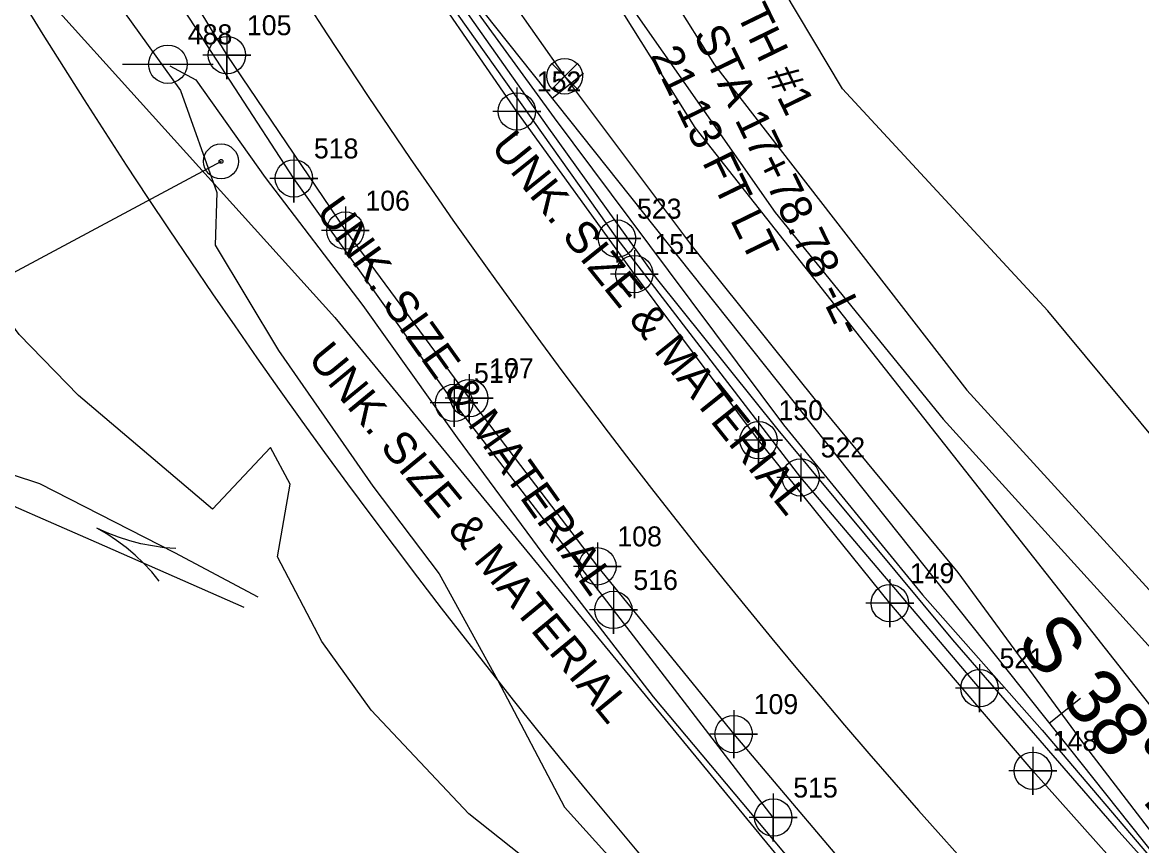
# Model space of a CAD drawing. Extents: x 1534145 to 1537876, y 509021 to 513201.
# Drawn here: x 1536125.4 to 1536265.6, y 511546.2 to 511649.3 of the extents above; entities that cross this region are included whole.
import ezdxf

# ---------------------------------------------------------------- set-up
doc = ezdxf.new("R2010")
doc.units = 0
for name, color, linetype in [('Exist Guardrail', 7, 'Continuous'), ('Exist Guardrail Cogo Number', 7, 'Continuous'), ('Exist Guardrail Cogo Point CELL', 7, 'Continuous'), ('Exist Horizontal Alignment', 7, 'Continuous'), ('Exist Horizontal Baseline Alignment', 7, 'Continuous'), ('Exist Horizontal Baseline Alignment Direction Label', 7, 'Continuous'), ('Exist Horizontal Baseline Alignment Tick small', 7, 'Continuous'), ('Exist Hydro Stream Flow Arrow CELL', 7, 'Continuous'), ('Exist Hydro Stream or Body of Water', 7, 'Continuous'), ('Exist Right of Way Line', 7, 'Continuous'), ('Exist Roads EOP', 7, 'Continuous'), ('Exist Roads EOP Cogo Number', 7, 'Continuous'), ('Exist Roads EOP Cogo Point CELL', 7, 'Continuous'), ('Exist Utilities Other Located Object CELL', 7, 'Continuous'), ('Exist Utilities Other Located Object Leader', 7, 'Continuous'), ('Exist Utilities Telephone Pole CELL', 7, 'Continuous'), ('Exist Utilities Telephone Pole Cogo Number', 7, 'Continuous'), ('Exist Utilities Telephone UG Cable', 7, 'Continuous'), ('Exist Utilities Telephone UG Cable Text', 7, 'Continuous'), ('Exist Utilities Telephone UG FO SUE', 7, 'Continuous'), ('Exist Utilities Telephone UG FO SUE Text', 7, 'Continuous'), ('Exist Utilities TV UG Cable', 7, 'Continuous'), ('Exist Utilities Water Test Hole SUE Text', 7, 'Continuous'), ('Exist Utilities Water UG Line SUE', 7, 'Continuous'), ('Exist Utilities Water Valve CELL', 7, 'Continuous'), ('Exist Vegetation Woods Line', 7, 'Continuous')]:
    doc.layers.add(name, color=color, linetype=linetype)

# ---------------------------------------------------------------- blocks, each defined once
blk = doc.blocks.new('EXIST UTILITIES TELEPHONE POLE')
at = {"layer": 'Exist Utilities Telephone Pole CELL'}
for p, q in [((-0.1135, 0), (0.11325, 0)), ((0, 0), (0, 0))]:
    blk.add_line(p, q, dxfattribs=at)
blk.add_circle((0, 0), 0.04813, dxfattribs=at)
blk = doc.blocks.new('EXIST UTILITIES OTHER LOCATED OBJECT')
at = {"layer": 'Exist Utilities Other Located Object CELL'}
for radius in [0.0436, 0.0048]:
    blk.add_circle((0, 0), radius, dxfattribs=at)

msp = doc.modelspace()

# ---------------------------------------------------------------- linework, layer by layer
at = {"layer": 'Exist Guardrail'}
for points in [[(1536245.27, 511565.91), (1536222.87, 511592.31), (1536199.87, 511622.21), (1536168.21, 511666.86), (1536157.96, 511682.31)], [(1536219.44, 511549.72), (1536199.42, 511575.71), (1536179.46, 511601.63), (1536159.41, 511629.75), (1536144.62, 511652.49), (1536134.97, 511668.45)]]:
    msp.add_lwpolyline(points, dxfattribs=at)
at = {"layer": 'Exist Guardrail Cogo Point CELL'}
for points in [[(1536159.41, 511632.75), (1536159.41, 511626.75), (1536159.41, 511629.75), (1536162.41, 511629.75), (1536156.41, 511629.75)], [(1536199.87, 511625.21), (1536199.87, 511619.21), (1536199.87, 511622.21), (1536202.87, 511622.21), (1536196.87, 511622.21)], [(1536179.46, 511604.63), (1536179.46, 511598.63), (1536179.46, 511601.63), (1536182.46, 511601.63), (1536176.46, 511601.63)], [(1536222.87, 511595.31), (1536222.87, 511589.31), (1536222.87, 511592.31), (1536225.87, 511592.31), (1536219.87, 511592.31)], [(1536199.42, 511578.71), (1536199.42, 511572.71), (1536199.42, 511575.71), (1536202.42, 511575.71), (1536196.42, 511575.71)], [(1536245.27, 511568.91), (1536245.27, 511562.91), (1536245.27, 511565.91), (1536248.27, 511565.91), (1536242.27, 511565.91)], [(1536219.44, 511552.72), (1536219.44, 511546.72), (1536219.44, 511549.72), (1536222.44, 511549.72), (1536216.44, 511549.72)]]:
    msp.add_lwpolyline(points, dxfattribs=at)
for centre in [(1536159.41, 511629.75), (1536199.87, 511622.21), (1536179.46, 511601.63), (1536222.87, 511592.31), (1536199.42, 511575.71), (1536245.27, 511565.91), (1536219.44, 511549.72)]:
    msp.add_circle(centre, 2.34, dxfattribs=at)
at = {"layer": 'Exist Horizontal Alignment'}
msp.add_arc((1536874.85, 512113.15), 850, 183.46397, 223.9944, dxfattribs=at)
at = {"layer": 'Exist Horizontal Baseline Alignment'}
msp.add_line((1536066.28, 511797.6), (1536449.44, 511315.8), dxfattribs=at)
at = {"layer": 'Exist Horizontal Baseline Alignment Tick small'}
for p, q in [((1536191.76, 511639.81), (1536195.67, 511642.93)), ((1536254, 511561.55), (1536257.92, 511564.66))]:
    msp.add_line(p, q, dxfattribs=at)
at = {"layer": 'Exist Hydro Stream Flow Arrow CELL'}
msp.add_line((1536139.14, 511583.67), (1536139.14, 511583.67), dxfattribs=at)
for points in [[(1536144.63, 511583.39), (1536143.17, 511583.48), (1536141.69, 511583.72), (1536140.24, 511583.99), (1536138.84, 511584.36), (1536137.43, 511584.82), (1536136.04, 511585.37), (1536134.71, 511585.97)], [(1536142.52, 511579.33), (1536141.61, 511580.48), (1536140.56, 511581.55), (1536139.51, 511582.59), (1536138.4, 511583.52), (1536137.21, 511584.4), (1536135.97, 511585.23), (1536134.71, 511585.97)]]:
    msp.add_lwpolyline(points, dxfattribs=at)
at = {"layer": 'Exist Hydro Stream or Body of Water'}
for points in [[(1536113.56, 511596.13), (1536127.55, 511591.56), (1536144.46, 511582.92), (1536154.87, 511577.37)], [(1536111.59, 511594.19), (1536118.18, 511591.38), (1536134.65, 511584.19), (1536153.12, 511576.06)]]:
    msp.add_lwpolyline(points, dxfattribs=at)
at = {"layer": 'Exist Right of Way Line'}
msp.add_lwpolyline([(1536145.81, 511737.79), (1536209.6, 511636.11), (1536268.44, 511561.44), (1536375.73, 511456.33), (1536489.24, 511358.86)], dxfattribs=at)
msp.add_arc((1536874.85, 512113.15), 880, 183.46397, 223.9944, dxfattribs=at)
at = {"layer": 'Exist Roads EOP'}
for points in [[(1536369.08, 511439.8), (1536328.72, 511476.49), (1536308.15, 511496.03), (1536288.57, 511515.64), (1536269.45, 511535.94), (1536251.94, 511555.57), (1536234.04, 511576.56), (1536217.6, 511596.97), (1536202.04, 511617.77), (1536187.32, 511638.14), (1536172.57, 511659.55), (1536157.27, 511681.68), (1536156.29, 511681.96)], [(1536135.62, 511669.8), (1536136.84, 511668.44), (1536151.02, 511645.18), (1536165.85, 511623.21), (1536181.37, 511602.23), (1536197.41, 511581.17), (1536214.48, 511560.17), (1536232.66, 511538.69), (1536250.52, 511518.58), (1536269.89, 511498.04), (1536290.03, 511477.85), (1536311.06, 511457.59), (1536352.37, 511420.24), (1536394.3, 511383.89), (1536395.14, 511383.19)]]:
    msp.add_lwpolyline(points, dxfattribs=at)
at = {"layer": 'Exist Roads EOP Cogo Point CELL'}
for points in [[(1536151.02, 511648.18), (1536151.02, 511642.18), (1536151.02, 511645.18), (1536154.02, 511645.18), (1536148.02, 511645.18)], [(1536187.32, 511641.14), (1536187.32, 511635.14), (1536187.32, 511638.14), (1536190.32, 511638.14), (1536184.32, 511638.14)], [(1536165.85, 511626.21), (1536165.85, 511620.21), (1536165.85, 511623.21), (1536168.85, 511623.21), (1536162.85, 511623.21)], [(1536202.04, 511620.77), (1536202.04, 511614.77), (1536202.04, 511617.77), (1536205.04, 511617.77), (1536199.04, 511617.77)], [(1536181.37, 511605.23), (1536181.37, 511599.23), (1536181.37, 511602.23), (1536184.37, 511602.23), (1536178.37, 511602.23)], [(1536217.6, 511599.97), (1536217.6, 511593.97), (1536217.6, 511596.97), (1536220.6, 511596.97), (1536214.6, 511596.97)], [(1536197.41, 511584.17), (1536197.41, 511578.17), (1536197.41, 511581.17), (1536200.41, 511581.17), (1536194.41, 511581.17)], [(1536234.04, 511579.56), (1536234.04, 511573.56), (1536234.04, 511576.56), (1536237.04, 511576.56), (1536231.04, 511576.56)], [(1536214.48, 511563.17), (1536214.48, 511557.17), (1536214.48, 511560.17), (1536217.48, 511560.17), (1536211.48, 511560.17)], [(1536251.94, 511558.57), (1536251.94, 511552.57), (1536251.94, 511555.57), (1536254.94, 511555.57), (1536248.94, 511555.57)]]:
    msp.add_lwpolyline(points, dxfattribs=at)
for centre in [(1536151.02, 511645.18), (1536187.32, 511638.14), (1536165.85, 511623.21), (1536202.04, 511617.77), (1536181.37, 511602.23), (1536217.6, 511596.97), (1536197.41, 511581.17), (1536234.04, 511576.56), (1536214.48, 511560.17), (1536251.94, 511555.57)]:
    msp.add_circle(centre, 2.34, dxfattribs=at)
at = {"layer": 'Exist Utilities Other Located Object Leader'}
msp.add_lwpolyline([(1536150.28, 511631.88), (1536117.14, 511614.12)], dxfattribs=at)
at = {"layer": 'Exist Utilities Telephone UG Cable'}
for p, q in [((1536175.52, 511659.96), (1536192.01, 511637.35)), ((1536175.22, 511658.83), (1536191.1, 511636.32)), ((1536192.01, 511637.35), (1536206.26, 511618.23)), ((1536191.1, 511636.32), (1536204.79, 511617.25)), ((1536204.79, 511617.25), (1536220, 511598.28)), ((1536206.26, 511618.23), (1536220.73, 511598.89)), ((1536220.73, 511598.89), (1536238.12, 511577.6)), ((1536220, 511598.28), (1536241.9, 511571.98)), ((1536238.12, 511577.6), (1536253.12, 511560.67)), ((1536241.9, 511571.98), (1536262.38, 511548.36)), ((1536253.12, 511560.67), (1536277.94, 511531.46)), ((1536262.38, 511548.36), (1536284.46, 511523.72))]:
    msp.add_line(p, q, dxfattribs=at)
msp.add_lwpolyline([(1536104.49, 511678.82), (1536164.53, 511612.35), (1536236.27, 511525.03), (1536297.08, 511464.63), (1536480.23, 511304.96), (1536615.57, 511192.85), (1536668.9, 511150.89)], dxfattribs=at)
at = {"layer": 'Exist Utilities Telephone UG FO SUE'}
for p, q in [((1536190.04, 511679.02), (1536212.07, 511643.97)), ((1536143.88, 511643.84), (1536147.11, 511642.1)), ((1536212.07, 511643.97), (1536243.68, 511603.25)), ((1536147.11, 511642.1), (1536155.8, 511629.85)), ((1536155.8, 511629.85), (1536168.04, 511613.83)), ((1536168.04, 511613.83), (1536179.84, 511597.26)), ((1536243.68, 511603.25), (1536277.87, 511565.77)), ((1536179.84, 511597.26), (1536190.58, 511582.72)), ((1536190.58, 511582.72), (1536204.41, 511564.85)), ((1536204.41, 511564.85), (1536223.81, 511541.74))]:
    msp.add_line(p, q, dxfattribs=at)
at = {"layer": 'Exist Utilities TV UG Cable'}
for p, q in [((1536201.03, 511652.14), (1536219.66, 511625.48)), ((1536219.66, 511625.48), (1536240.7, 511599.58)), ((1536240.7, 511599.58), (1536262.03, 511576.08)), ((1536262.03, 511576.08), (1536294.78, 511539.93))]:
    msp.add_line(p, q, dxfattribs=at)
at = {"layer": 'Exist Utilities Water UG Line SUE'}
for p, q in [((1536179.48, 511662.22), (1536193.31, 511642.54)), ((1536193.31, 511642.54), (1536209.43, 511621.02)), ((1536209.43, 511621.02), (1536225, 511601.61)), ((1536225, 511601.61), (1536242.56, 511580.39)), ((1536242.56, 511580.39), (1536258.52, 511558.6)), ((1536258.52, 511558.6), (1536273.92, 511538.52))]:
    msp.add_line(p, q, dxfattribs=at)
at = {"layer": 'Exist Utilities Water Valve CELL'}
msp.add_lwpolyline([(1536194.89, 511644.11), (1536191.74, 511640.96), (1536193.31, 511642.54), (1536194.89, 511640.96), (1536191.74, 511644.11)], dxfattribs=at)
msp.add_circle((1536193.31, 511642.54), 2.23, dxfattribs=at)
at = {"layer": 'Exist Vegetation Woods Line'}
for points in [[(1536364.55, 511576.16), (1536373, 511565.43), (1536358.52, 511548.6), (1536355.99, 511534.94), (1536336.01, 511558.77), (1536332.84, 511549.1), (1536313.82, 511551.08), (1536307.55, 511548.5), (1536253.81, 511613.18), (1536228.12, 511640.97), (1536207.73, 511675.11), (1536230.48, 511698.35), (1536246.44, 511712.1), (1536224.35, 511724.34), (1536209.33, 511733.76), (1536195.78, 511706.5), (1536177.81, 511692.48), (1536173.01, 511708.97), (1536159.67, 511734.26)], [(1536132.43, 511602.57), (1536124.99, 511610.21), (1536118.41, 511619.12), (1536111.25, 511624.87), (1536100.82, 511631.28), (1536101.8, 511638.77), (1536103.38, 511647.62), (1536105.83, 511652.14), (1536101.42, 511660.69), (1536101.55, 511667.15), (1536100.65, 511672.64), (1536101.75, 511677.35), (1536103.52, 511683.54), (1536105.65, 511690.76), (1536107.05, 511696.01)], [(1536109.6, 511695.77), (1536115.59, 511681.18), (1536116.46, 511672.95), (1536121.81, 511662.79), (1536133.05, 511657.69), (1536145.22, 511640.75), (1536149.74, 511627.98), (1536149.55, 511621.39), (1536157.47, 511608.2), (1536169.29, 511591.2), (1536177.58, 511580.25), (1536184.9, 511566.94), (1536193.3, 511551.02), (1536202.62, 511540.69), (1536202.07, 511534.62), (1536190.4, 511542.98), (1536181.32, 511550.16), (1536169.1, 511563.16), (1536162.92, 511571.77), (1536157.34, 511582.36), (1536158.92, 511591.44), (1536156.48, 511596.06), (1536149.2, 511588.33), (1536132.43, 511602.57)]]:
    msp.add_lwpolyline(points, dxfattribs=at)

# ---------------------------------------------------------------- block references
at = {"layer": 'Exist Utilities Other Located Object CELL', "xscale": 50, "yscale": 50}
msp.add_blockref('EXIST UTILITIES OTHER LOCATED OBJECT', (1536150.28, 511631.88), dxfattribs=at)
at = {"layer": 'Exist Utilities Telephone Pole CELL', "xscale": 50, "yscale": 50}
msp.add_blockref('EXIST UTILITIES TELEPHONE POLE', (1536143.62, 511644.04), dxfattribs=at)

# ---------------------------------------------------------------- texts
at = {"layer": 'Exist Guardrail Cogo Number'}
for s, p in [('518', (1536161.91, 511632.25)), ('523', (1536202.37, 511624.71)), ('517', (1536181.96, 511604.13)), ('522', (1536225.37, 511594.81)), ('516', (1536201.92, 511578.21)), ('521', (1536247.77, 511568.41)), ('515', (1536221.94, 511552.22))]:
    msp.add_text(s, height=2.5, dxfattribs=at).set_placement(p)
at = {"layer": 'Exist Horizontal Baseline Alignment Direction Label'}
msp.add_text('S 38%%d 29\' 40.1" E', height=7, rotation=308.4945, dxfattribs=at).set_placement((1536249.73, 511571.7))
at = {"layer": 'Exist Roads EOP Cogo Number'}
for s, p in [('105', (1536153.52, 511647.68)), ('152', (1536189.82, 511640.64)), ('106', (1536168.35, 511625.71)), ('151', (1536204.54, 511620.27)), ('107', (1536183.87, 511604.73)), ('150', (1536220.1, 511599.47)), ('108', (1536199.91, 511583.67)), ('149', (1536236.54, 511579.06)), ('109', (1536216.98, 511562.67)), ('148', (1536254.44, 511558.07))]:
    msp.add_text(s, height=2.5, dxfattribs=at).set_placement(p)
at = {"layer": 'Exist Utilities Telephone Pole Cogo Number'}
msp.add_text('488', height=2.5, dxfattribs=at).set_placement((1536146.12, 511646.54))
at = {"layer": 'Exist Utilities Telephone UG Cable Text'}
for rotation, p in [(308.7202, (1536183.94, 511633.67)), (309.4041, (1536161.03, 511607.15))]:
    msp.add_text('UNK. SIZE & MATERIAL', height=4, rotation=rotation, dxfattribs=at).set_placement(p)
at = {"layer": 'Exist Utilities Telephone UG FO SUE Text'}
msp.add_text('UNK. SIZE & MATERIAL', height=4, rotation=305.4833, dxfattribs=at).set_placement((1536162.07, 511625.63))
at = {"layer": 'Exist Utilities Water Test Hole SUE Text'}
for s, p in [('TH #1', (1536214.76, 511650.41)), ('STA 17+78.78 -L-', (1536209.37, 511647.79)), ('21.13 FT LT', (1536203.97, 511645.16))]:
    msp.add_text(s, height=4, rotation=295.9542, dxfattribs=at).set_placement(p)

doc.saveas('drawing.dxf')
